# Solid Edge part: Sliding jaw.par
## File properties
Title: Sliding Jaw
Author: Abhinav Rai
Template: Normal.par
Last saved by: CADCIM
Revision: 18
Application: Solid Edge
Density: 0.0000078 kg/mm^3
Accuracy: 0.01
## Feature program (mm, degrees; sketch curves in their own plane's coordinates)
sketch used by "unnamed Protrusion 1" plane through (0, 0, 0) normal (0, -1, 0) x-axis (1, 0, 0)
  line (-34.0632, 44.45) -> (-34.0632, 0)
  line (-34.0632, 0) -> (5.6116, 0)
  line (5.6116, 0) -> (5.6116, 19.9608)
  line (-34.0632, 44.45) -> (-19.6102, 44.45)
  arc centre (-37.2382, 14.3002) radius 34.925 from (-19.6102, 44.45) to (-3.8245, 24.463) cw
  arc centre (2.2507, 26.3108) radius 6.35 from (-3.8245, 24.463) to (2.2507, 19.9608) ccw
  line (5.6116, 19.9608) -> (2.2507, 19.9608)
  dimension (linear) = 37.2382
extrude "unnamed Protrusion 1" add finite 69.7992 symmetric
sketch for "ExtrudedProtrusion_2" plane through (5.6116, 0, 9.9804) normal (1, 0, 0) x-axis (0, 1, 0)
extrude "ExtrudedProtrusion_2" add finite 65.0748 along -normal
sketch for "unnamed Cutout 1" plane through (-26.9258, -15.24, -27.8638) normal (0, -1, 0) x-axis (1, 0, 0)
extrude "unnamed Cutout 1" cut through along -normal
sketch for "unnamed Protrusion 2" plane through (5.6116, 0, -9.0696) normal (1, 0, 0) x-axis (0, 1, 0)
  arc centre (0, 26.5956) radius 23.9515 from (-23.8274, 29.0304) to (23.8274, 29.0304) cw
  line (-23.8274, 29.0304) -> (23.8274, 29.0304)
extrude "unnamed Protrusion 2" add through along -normal
sketch for "Hole_1" plane through (5.6116, 0, -0.1583) normal (1, 0, 0) x-axis (0, 1, 0)
hole "Hole_1" diameter 19.05 through
fillet "Round_1" radius 3.175
sketch for "Hole_2" plane through (-26.9258, 0, -38.1) normal (0, 0, -1) x-axis (0, 1, 0)
  hole centre (7.9375, 2.3876) bore radius 2.7686
hole "Hole_2" diameter 5.5372 finite
sketch for "unnamed Hole 1" plane through (-26.9258, 0, -38.1) normal (0, 0, -1) x-axis (0, 1, 0)
  hole centre (-7.9375, 2.3876) bore radius 2.7686
hole "unnamed Hole 1" finite
sketch for "Hole_4" plane through (-34.0632, 0, 22.225) normal (-1, 0, 0) x-axis (0, -1, 0)
  hole centre (19.0754, 3.175) bore radius 3.175
hole "Hole_4" diameter 6.35 finite
sketch for "unnamed Hole 2" plane through (-34.0632, 0, 22.225) normal (-1, 0, 0) x-axis (0, -1, 0)
  hole centre (-19.0246, 3.175) bore radius 3.175
  dimension (linear) = 19.0246
hole "unnamed Hole 2" finite
pattern "unnamed Pattern 1" of "Hole_2", "unnamed Hole 1"
pattern "unnamed Pattern 2" of "Hole_4", "unnamed Hole 2"
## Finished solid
Body 1: solid body, 48 faces, 109 edges, 62 vertices.
  Faces by surface: plane 26, cylinder 16, torus 4, sphere 2
  Edges by curve: line 69, circle 33, intersection 7
Bounding box of the edges (mm; curved faces can reach further): 65.075 x 69.799 x 82.550, from (-59.4632, -34.8996, -38.1) to (5.6116, 34.8996, 44.45).
Cylindrical faces by radius (mm): R2.7686 x2, R3.1242 x1, R3.175 x8, R6.35 x2, R9.525 x1, R23.9515 x1, R34.925 x1
Toroidal faces (ring radius, tube radius in mm): R9.525 r3.175 x2, R31.75 r3.175 x2
Spherical faces by radius (mm): R3.175 x2
Planar faces by outward normal: +x 1, +y 4, +z 6, -x 3, -y 4, -z 7, oblique 1
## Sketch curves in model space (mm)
line (-34.0632, 0, 0) -> (5.6116, 0, 0)
line (5.6116, 0, 0) -> (5.6116, 0, 19.9608)
line (5.6116, 0, 19.9608) -> (2.2507, 0, 19.9608)
arc centre (2.2507, 0, 26.3108) radius 6.35 from (-3.8245, 0, 24.463) through (-1.5301, 0, 21.209) to (2.2507, 0, 19.9608)
arc centre (-37.2382, 0, 14.3002) radius 34.925 from (-19.6102, 0, 44.45) through (-9.8305, 0, 35.9468) to (-3.8245, 0, 24.463)
line (-34.0632, 0, 44.45) -> (-19.6102, 0, 44.45)
line (-34.0632, 0, 44.45) -> (-34.0632, 0, 0)
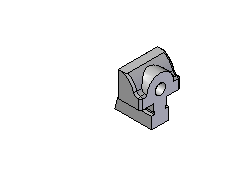
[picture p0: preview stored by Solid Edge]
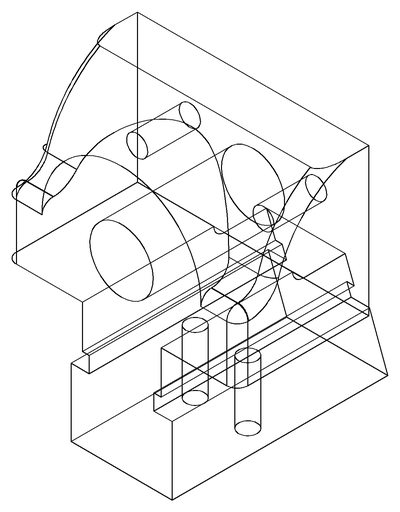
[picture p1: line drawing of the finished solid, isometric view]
